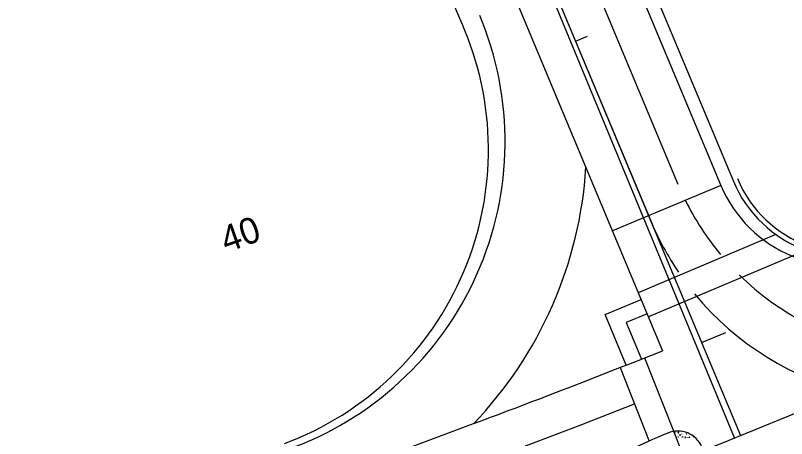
# Model space of a CAD drawing. Extents: x 2339272 to 2351734, y 366540 to 375057.
# Drawn here: x 2348390.9 to 2348627, y 367683.6 to 367813.2 of the extents above; entities that cross this region are included whole.
import ezdxf

# ---------------------------------------------------------------- set-up
doc = ezdxf.new("R2010")
doc.units = 0
for name, color, linetype in [('RD_HC_Cl', 7, 'Continuous'), ('RD_HC_CL_Rel', 7, 'Continuous'), ('RD_HC_Data_Tic_Rel', 7, 'Continuous'), ('RD_HC_TX_Sta50', 7, 'Continuous'), ('RD_PD_ConcMed', 7, 'Continuous'), ('RD_PD_Final_LnLine', 7, 'Continuous'), ('RD_PD_Final_TrvlWay', 7, 'Continuous'), ('RD_PD_FOC', 7, 'Continuous'), ('RD_PD_PaveShd', 7, 'Continuous')]:
    doc.layers.add(name, color=color, linetype=linetype)

msp = doc.modelspace()

# ---------------------------------------------------------------- linework, layer by layer
at = {"layer": 'RD_HC_Cl'}
msp.add_arc((2347533.93, 370355.68), 2880.79, 281.44073, 295.94073, dxfattribs=at)
at = {"layer": 'RD_HC_CL_Rel'}
msp.add_line((2348345.74, 368322.92), (2348612.9, 367684.58), dxfattribs=at)
at = {"layer": 'RD_HC_Data_Tic_Rel'}
for p, q in [((2348562.38, 367805.3), (2348566.07, 367806.85)), ((2348600.98, 367713.06), (2348608.36, 367716.15))]:
    msp.add_line(p, q, dxfattribs=at)
at = {"layer": 'RD_PD_ConcMed'}
for p, q in [((2348571.4, 367721.58), (2348582.47, 367726.21)), ((2348577.87, 367706.13), (2348571.4, 367721.58)), ((2348584.29, 367721.86), (2348577.84, 367719.15)), ((2348577.84, 367719.15), (2348582.52, 367707.97)), ((2348591.68, 367685.65), (2348591.69, 367685.71)), ((2348592.31, 367685.97), (2348598.14, 367671.16)), ((2348593.25, 367685.51), (2348593.27, 367685.47)), ((2348593.6, 367684.67), (2348593.61, 367684.72)), ((2348593.77, 367685.17), (2348593.81, 367685.14)), ((2348593.8, 367685.16), (2348593.83, 367685.14)), ((2348594.91, 367685), (2348594.92, 367685.05)), ((2348595.15, 367685.66), (2348595.16, 367685.71)), ((2348595.68, 367684.9), (2348595.72, 367684.87)), ((2348596.11, 367685.56), (2348596.11, 367685.58)), ((2348596.97, 367684.48), (2348596.97, 367684.53)), ((2348597.84, 367684.54), (2348597.84, 367684.6)), ((2348593.18, 367684.01), (2348593.21, 367683.98)), ((2348595.33, 367683.65), (2348595.34, 367683.71)), ((2348596.62, 367683.96), (2348596.64, 367683.92)), ((2348598.53, 367684.11), (2348598.53, 367684.16))]:
    msp.add_line(p, q, dxfattribs=at)
for points in [[(2348592.61, 367685.38), (2348592.55, 367685.69), (2348592.8, 367685.56), (2348592.62, 367685.38)], [(2348593.8, 367685.48), (2348593.81, 367685.63), (2348593.95, 367685.59), (2348593.8, 367685.48)], [(2348594.26, 367684.61), (2348594.3, 367684.92), (2348594.5, 367684.72), (2348594.26, 367684.61)], [(2348595.06, 367684.1), (2348595.07, 367684.25), (2348595.2, 367684.21), (2348595.06, 367684.1)], [(2348596.28, 367684.96), (2348596.3, 367685.11), (2348596.43, 367685.07), (2348596.28, 367684.96)], [(2348593.78, 367684.06), (2348593.79, 367684.22), (2348593.93, 367684.18), (2348593.78, 367684.06)], [(2348595.99, 367683.82), (2348595.92, 367684.14), (2348596.18, 367684.01), (2348595.99, 367683.83)], [(2348597.17, 367683.93), (2348597.19, 367684.08), (2348597.32, 367684.04), (2348597.17, 367683.93)]]:
    msp.add_lwpolyline(points, dxfattribs=at)
at = {"layer": 'RD_PD_Final_LnLine'}
for p, q in [((2348343.52, 368328.22), (2348585.38, 367750.35)), ((2348611.02, 367683.86), (2348357, 368298.46)), ((2348611.02, 367683.86), (2348357, 368298.46)), ((2348611.02, 367683.86), (2348357, 368298.46)), ((2348611.02, 367683.86), (2348357, 368298.46)), ((2348467.49, 368063.09), (2348593.69, 367761.57)), ((2348507.65, 367904.98), (2348565.56, 367766.61)), ((2348565.56, 367766.61), (2348589.02, 367710.55)), ((2348606.89, 367761.11), (2348573.68, 367747.21)), ((2348623.71, 367746.13), (2348581.57, 367728.3)), ((2348632.85, 367741.31), (2348584.68, 367720.93)), ((2348583.45, 367708.33), (2348592.31, 367685.97)), ((2348576.01, 367705.39), (2348584.92, 367682.88))]:
    msp.add_line(p, q, dxfattribs=at)
for centre, radius, start, end in [((2348440.82, 367774.57), 125, 316.2975, 356.3479), ((2348672.1, 367794.39), 85, 206.4376, 219.7463), ((2348668.4, 367785.09), 90, 202.7108, 214.1247), ((2348672.1, 367794.39), 85, 225.4757, 293.9591), ((2348668.4, 367785.09), 90, 219.3713, 293.8132), ((2347533.93, 370355.68), 2847.79, 290.49863, 291.74619), ((2347533.93, 370355.68), 2859.79, 280.38027, 291.4654), ((2347533.93, 370355.68), 2847.79, 280.38027, 290.49863), ((2348779.03, 367243.82), 480.06, 113.1133, 119.5832), ((2348593.67, 367677.96), 8, 292.7108, 112.7108)]:
    msp.add_arc(centre, radius, start, end, dxfattribs=at)
at = {"layer": 'RD_PD_Final_TrvlWay'}
msp.add_line((2348478.33, 368068.28), (2348606.89, 367761.11), dxfattribs=at)
for centre, radius, start, end in [((2348440.82, 367774.57), 100, 289.3592, 22.7108), ((2348643.79, 367776.55), 40, 202.7108, 293.2834)]:
    msp.add_arc(centre, radius, start, end, dxfattribs=at)
at = {"layer": 'RD_PD_FOC'}
msp.add_arc((2348645.98, 367777.31), 36.82, 202.4916, 298.2664, dxfattribs=at)
at = {"layer": 'RD_PD_PaveShd'}
for p, q in [((2348481.97, 368069.95), (2348610.58, 367762.65)), ((2348527.53, 367810.86), (2348490.97, 367898.21))]:
    msp.add_line(p, q, dxfattribs=at)
for centre, radius, start, end in [((2348439.7, 367772.06), 96.02, 290.4849, 23.8364), ((2348645.98, 367777.31), 38.32, 202.4916, 298.2664)]:
    msp.add_arc(centre, radius, start, end, dxfattribs=at)

# ---------------------------------------------------------------- texts
at = {"layer": 'RD_HC_TX_Sta50'}
msp.add_text('40', height=8, rotation=19.5309, dxfattribs=at).set_placement((2348455.45, 367740.49))

doc.saveas('drawing.dxf')
